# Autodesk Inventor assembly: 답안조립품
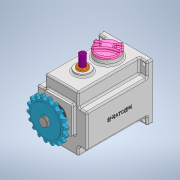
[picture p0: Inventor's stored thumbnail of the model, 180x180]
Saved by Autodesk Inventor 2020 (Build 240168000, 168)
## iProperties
Created: 2022-01
Part Number: 답안조립품
Document SubType Name: Assembly
Designer: user
Author: user
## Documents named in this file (16)
- C:\Users\user\Desktop\720112V1011\답안조립품.iam
- C:\Users\user\Desktop\720112V1011\본체.ipt
- C:\Users\user\Desktop\720112V1011\볼트 M4 x 10.ipt
- C:\Users\user\Desktop\720112V1011\부시.ipt
- C:\Users\user\Desktop\720112V1011\상부 캡.ipt
- C:\Users\user\Desktop\720112V1011\서브 축.ipt
- C:\Users\user\Desktop\720112V1011\스프로킷.ipt
- C:\Users\user\Desktop\720112V1011\슬라이더.ipt
- C:\Users\user\Desktop\720112V1011\오일 실 8 x 22 x 7.ipt
- C:\Users\user\Desktop\720112V1011\오일 실 17 x 32 x 8.ipt
- C:\Users\user\Desktop\720112V1011\커버.ipt
- C:\Users\user\Desktop\720112V1011\키 5 x 5.ipt
- C:\Users\user\Desktop\720112V1011\멈춤나사 M3.ipt
- C:\Users\user\Desktop\720112V1011\메인 축.ipt
- C:\Users\user\Desktop\720112V1011\베어링 608.ipt
- C:\Users\user\Desktop\720112V1011\베어링 6003.ipt
